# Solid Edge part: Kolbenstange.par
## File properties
Username: bmolnar
Dokumentum tartalom típus: 0
Author: bmolnar
Last saved by: bmolnar
Revision: 98
Sűrűség: 0,000 kg/m^3
Pontosság: 0,990
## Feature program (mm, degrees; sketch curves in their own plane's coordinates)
base feature "unnamed BaseFeature 1"
sketch for "unnamed Protrusion 1" plane through (62.5, 0, 0) normal (1, 0, 0) x-axis (0, 0, -1)
  circle centre (0, 0) radius 50
extrude "unnamed Protrusion 1" add finite 14 along +normal
thread "unnamed Thread 1"
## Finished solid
Body 1: solid body, 17 faces, 23 edges, 8 vertices.
  Faces by surface: plane 8, cylinder 4, torus 3, cone 2
  Edges by curve: circle 13, line 6, ellipse 2, intersection 2
Bounding box of the edges (mm; curved faces can reach further): 471.500 x 100.000 x 100.000, from (-395, -50, -50) to (76.5, 50, 50).
Cylindrical faces by radius (mm): R7 x1, R8 x1, R12.5 x1, R50 x1
Conical faces (half-angle, radius in mm at the cone's reference point): 20 deg R7.4 x1, 60 deg R7.6 x1
Toroidal faces (ring radius, tube radius in mm): R7.4 r0.4 x2, R10.7 r1.8 x1
Planar faces by outward normal: +x 1, +z 1, -x 3, -z 1, oblique 2
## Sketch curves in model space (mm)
circle centre (62.5, 0, 0) radius 50
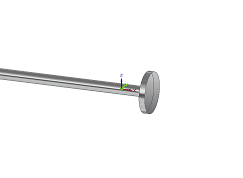
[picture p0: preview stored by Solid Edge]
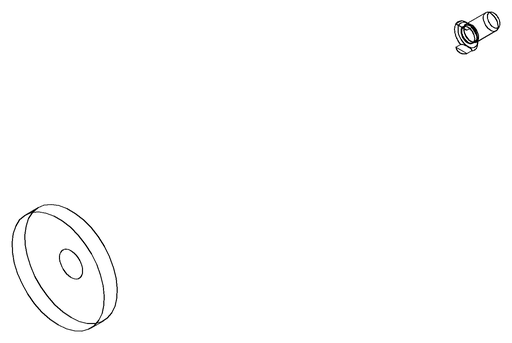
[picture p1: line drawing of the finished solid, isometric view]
